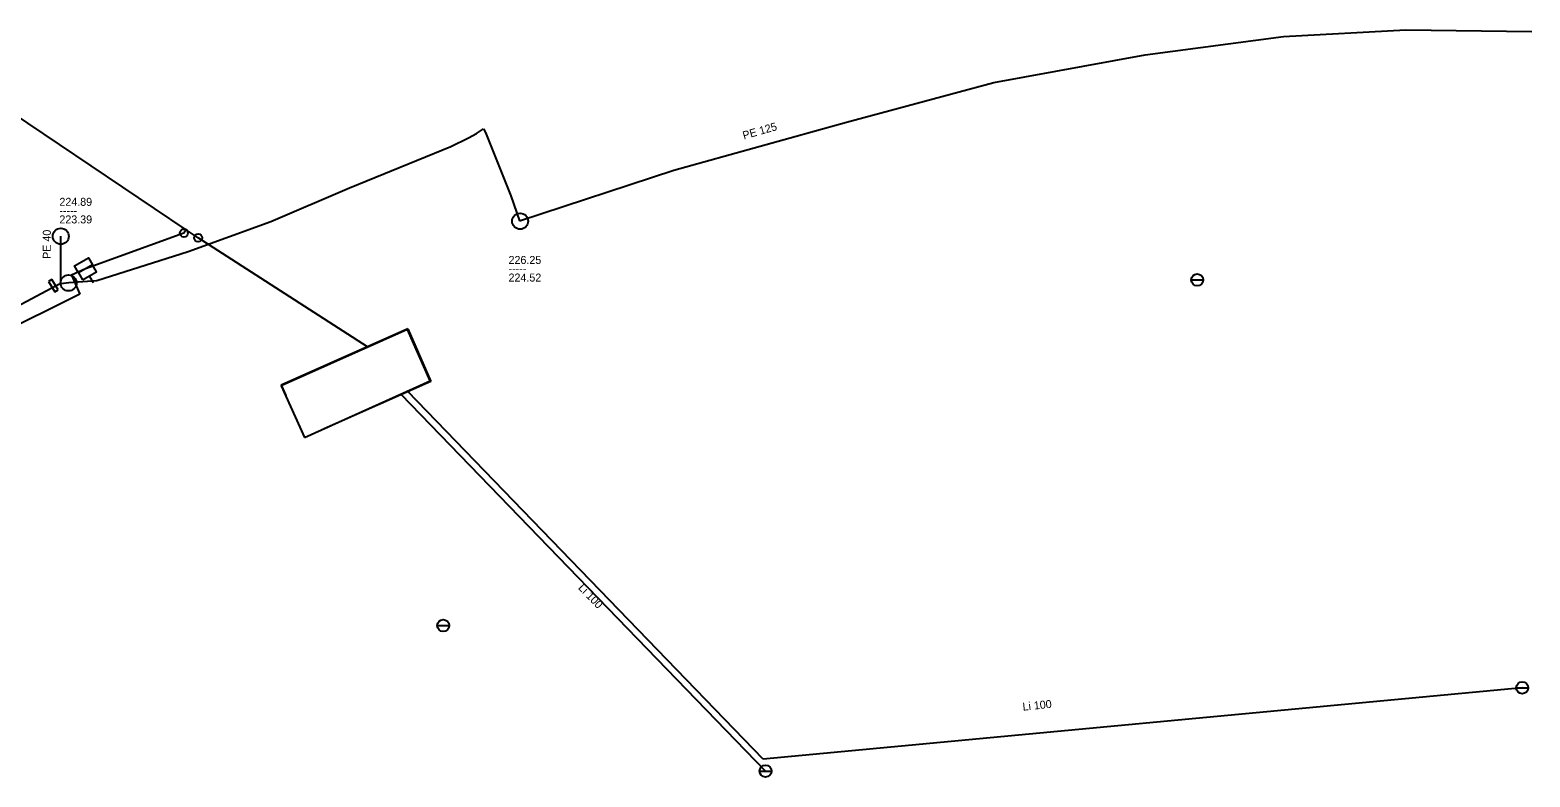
# Model space of a CAD drawing. Extents: x -771212 to -769571, y -1050452 to -1050119.
# Drawn here: x -770117.6 to -769930.2, y -1050246.3 to -1050152.8 of the extents above; entities that cross this region are included whole.
import ezdxf

# ---------------------------------------------------------------- set-up
doc = ezdxf.new("R2010")
doc.units = 0
doc.layers.add('Level 0', color=7, linetype='Continuous')

msp = doc.modelspace()

# ---------------------------------------------------------------- linework, layer by layer
at = {"layer": 'Level 0'}
for p, q in [((-769960.97, -1050153.67), (-769945.65, -1050152.84)), ((-769945.65, -1050152.84), (-769929.94, -1050153.01)), ((-769978.26, -1050155.94), (-769960.97, -1050153.67)), ((-769997.15, -1050159.42), (-769978.26, -1050155.94)), ((-770098.12, -1050177.82), (-770125.33, -1050159.5)), ((-770015.6, -1050164.37), (-769997.15, -1050159.42)), ((-770037.17, -1050170.36), (-770015.6, -1050164.37)), ((-770065.05, -1050167.42), (-770062.83, -1050166.33)), ((-770062.83, -1050166.33), (-770061.83, -1050165.77)), ((-770061.83, -1050165.77), (-770060.95, -1050165.21)), ((-770060.95, -1050165.21), (-770060.7, -1050165.67)), ((-770060.7, -1050165.67), (-770057.53, -1050173.57)), ((-770077.72, -1050172.59), (-770065.05, -1050167.42)), ((-770056.46, -1050176.71), (-770037.17, -1050170.36)), ((-770087.55, -1050176.81), (-770077.72, -1050172.59)), ((-770057.53, -1050173.57), (-770056.46, -1050176.71)), ((-770098.12, -1050177.82), (-770098.4, -1050178.23)), ((-770096.62, -1050178.83), (-770098.12, -1050177.82)), ((-770097.87, -1050180.56), (-770087.55, -1050176.81)), ((-770113.79, -1050184.56), (-770113.79, -1050178.64)), ((-770098.4, -1050178.23), (-770110.7, -1050182.71)), ((-770075.47, -1050192.46), (-770096.62, -1050178.83)), ((-770109.26, -1050184.15), (-770097.87, -1050180.56)), ((-770110.7, -1050182.71), (-770112.46, -1050183.49)), ((-770124.79, -1050190.31), (-770114.26, -1050184.77)), ((-770114.9, -1050184.04), (-770115.32, -1050184.29)), ((-770115.32, -1050184.29), (-770114.52, -1050185.6)), ((-770114.1, -1050185.35), (-770114.9, -1050184.04)), ((-770114.26, -1050184.77), (-770114.04, -1050184.64)), ((-770114.04, -1050184.64), (-770113.79, -1050184.56)), ((-770113.79, -1050184.56), (-770112.77, -1050184.4)), ((-770112.77, -1050184.4), (-770109.26, -1050184.15)), ((-770112.46, -1050183.49), (-770111.4, -1050185.86)), ((-770109.7, -1050184.44), (-770110.2, -1050183.58)), ((-769972.48, -1050184.09), (-769970.98, -1050184.09)), ((-770111.4, -1050185.86), (-770147.26, -1050203.69)), ((-770114.52, -1050185.6), (-770114.1, -1050185.35)), ((-770070.45, -1050190.3), (-770086.25, -1050197.33)), ((-770070.42, -1050190.22), (-770086.23, -1050197.25)), ((-770067.6, -1050196.7), (-770070.45, -1050190.3)), ((-770070.42, -1050190.22), (-770067.52, -1050196.79)), ((-770086.25, -1050197.33), (-770083.31, -1050203.82)), ((-770086.23, -1050197.25), (-770085.65, -1050198.57)), ((-770083.31, -1050203.82), (-770067.6, -1050196.7)), ((-770067.52, -1050196.79), (-770080.86, -1050202.71)), ((-770025.7, -1050245.51), (-770071.24, -1050198.44)), ((-770026.01, -1050244.03), (-770070.41, -1050198.07)), ((-770066.73, -1050227.32), (-770065.23, -1050227.32)), ((-769931.11, -1050235.1), (-770026.01, -1050244.03)), ((-769931.86, -1050235.1), (-769930.36, -1050235.1)), ((-770026.45, -1050245.51), (-770024.95, -1050245.51))]:
    msp.add_line(p, q, dxfattribs=at)
msp.add_lwpolyline([(-770111.57, -1050183.21), (-770112.07, -1050182.34), (-770110.33, -1050181.34), (-770109.83, -1050182.21)], dxfattribs=at)
msp.add_lwpolyline([(-770111.07, -1050184.08), (-770109.33, -1050183.08), (-770109.83, -1050182.21), (-770111.57, -1050183.21)], close=True, dxfattribs=at)
for centre, radius in [((-770056.37, -1050176.75), 1), ((-770113.79, -1050178.64), 1), ((-770098.4, -1050178.23), 0.5), ((-770096.62, -1050178.83), 0.5), ((-769971.73, -1050184.09), 0.75), ((-770112.82, -1050184.48), 1), ((-770065.98, -1050227.32), 0.75), ((-769931.11, -1050235.1), 0.75), ((-770025.7, -1050245.51), 0.75)]:
    msp.add_circle(centre, radius, dxfattribs=at)

# ---------------------------------------------------------------- texts
for s, rotation, p in [('PE 125', 15.918, (-770028.4, -1050166.54)), ('PE 40', 90, (-770115.03, -1050181.46)), ('Li 100', 314.054, (-770049.19, -1050222.67)), ('Li 100', 5.846, (-769993.52, -1050237.97))]:
    msp.add_text(s, height=1, rotation=rotation, dxfattribs=at).set_placement(p)
for s, p in [('224.89', (-770113.96, -1050174.83)), ('-----', (-770113.96, -1050175.93)), ('223.39', (-770113.96, -1050177.03)), ('226.25', (-770057.82, -1050182.1)), ('-----', (-770057.82, -1050183.2)), ('224.52', (-770057.82, -1050184.3))]:
    msp.add_text(s, height=1, dxfattribs=at).set_placement(p)

doc.saveas('drawing.dxf')
